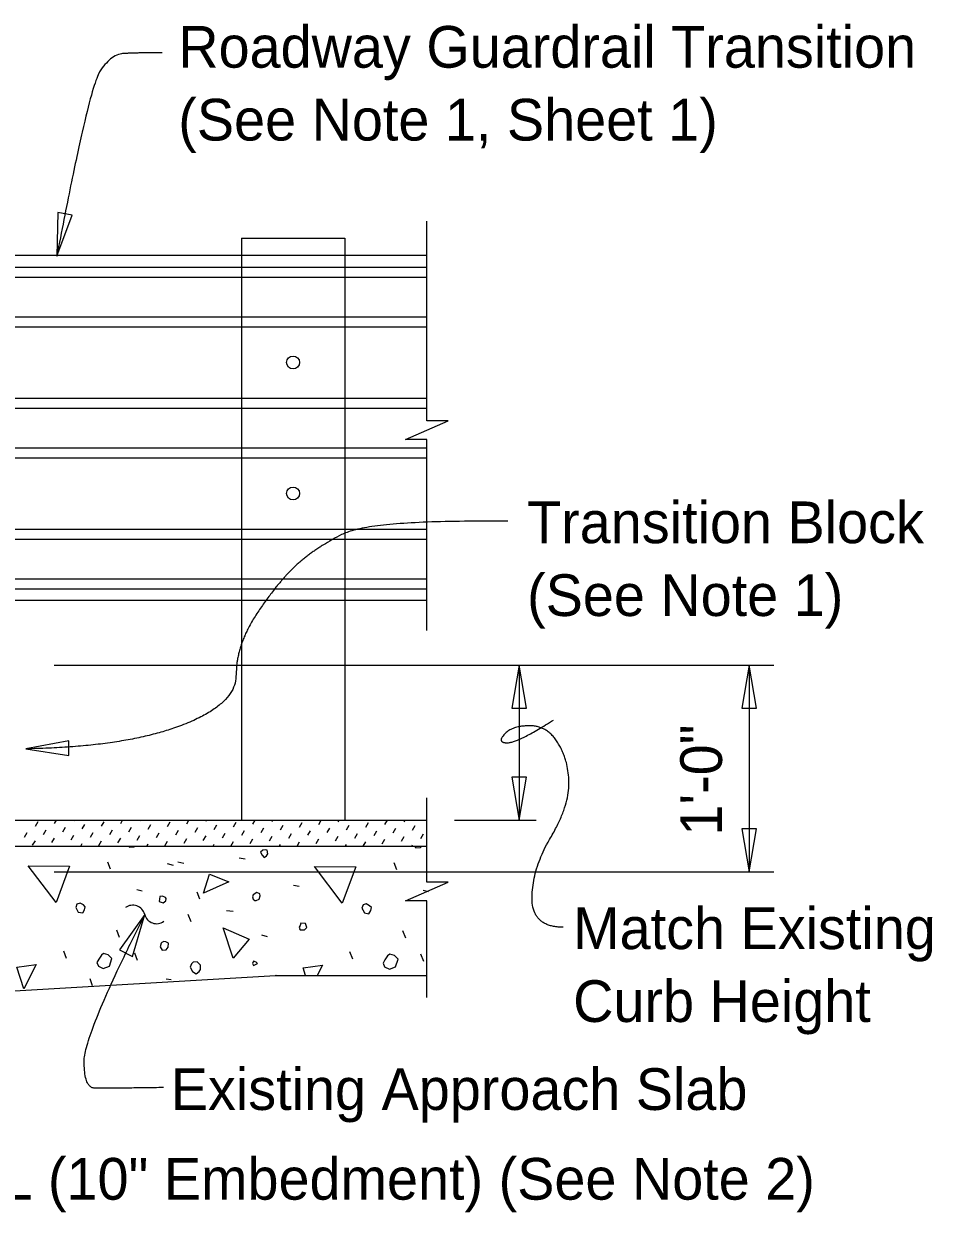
# Model space of a CAD drawing. Extents: x 21526.6 to 21598.7, y 56118.9 to 56155.9.
# Drawn here: x 21539.73 to 21544.13, y 56132.57 to 56138.31 of the extents above; entities that cross this region are included whole.
import ezdxf

# ---------------------------------------------------------------- set-up
doc = ezdxf.new("R2010")
doc.units = 0
for name, color, linetype in [('AdhocPoint_dp', 7, 'Continuous'), ('Border', 7, 'Continuous'), ('Patterning', 7, 'Continuous'), ('PlotBorder_dp', 7, 'Continuous'), ('SheetBorder_dp', 7, 'Continuous')]:
    doc.layers.add(name, color=color, linetype=linetype)

msp = doc.modelspace()

# ---------------------------------------------------------------- linework, layer by layer
at = {"layer": 'AdhocPoint_dp'}
for p, q in [((21535.7321, 56134.4601), (21541.6829, 56134.4601)), ((21537.6185, 56134.335), (21541.6829, 56134.335)), ((21536.7321, 56133.4601), (21540.9521, 56133.71)), ((21540.9521, 56133.7101), (21541.6829, 56133.7101))]:
    msp.add_line(p, q, dxfattribs=at)
at = {"layer": 'Patterning'}
for p, q in [((21540.7867, 56137.2725), (21540.7867, 56134.4601)), ((21540.7867, 56137.2725), (21541.2867, 56137.2725)), ((21541.2867, 56137.2725), (21541.2867, 56134.4601)), ((21539.7909, 56134.4317), (21539.8039, 56134.4541)), ((21539.884, 56134.4447), (21539.8929, 56134.46)), ((21539.9771, 56134.4577), (21539.9785, 56134.46)), ((21540.1103, 56134.4306), (21540.1232, 56134.4529)), ((21540.2034, 56134.4435), (21540.2129, 56134.46)), ((21540.2965, 56134.4565), (21540.2985, 56134.46)), ((21540.4297, 56134.4294), (21540.4426, 56134.4518)), ((21540.5228, 56134.4423), (21540.533, 56134.46)), ((21540.6159, 56134.4553), (21540.6186, 56134.46)), ((21540.749, 56134.4282), (21540.762, 56134.4506)), ((21540.8421, 56134.4412), (21540.8531, 56134.46)), ((21540.9352, 56134.4541), (21540.9387, 56134.46)), ((21541.0684, 56134.427), (21541.0814, 56134.4494)), ((21541.1615, 56134.44), (21541.1731, 56134.46)), ((21541.2546, 56134.4529), (21541.2587, 56134.46)), ((21541.3878, 56134.4258), (21541.4008, 56134.4482)), ((21541.4809, 56134.4388), (21541.4932, 56134.46)), ((21541.574, 56134.4518), (21541.5788, 56134.46)), ((21539.7379, 56134.3787), (21539.7508, 56134.4011)), ((21539.831, 56134.3917), (21539.8439, 56134.4141)), ((21539.9241, 56134.4046), (21539.937, 56134.427)), ((21539.9641, 56134.3646), (21539.9771, 56134.387)), ((21540.0172, 56134.4176), (21540.0301, 56134.44)), ((21540.0572, 56134.3775), (21540.0702, 56134.3999)), ((21540.1504, 56134.3905), (21540.1633, 56134.4129)), ((21540.2435, 56134.4034), (21540.2564, 56134.4258)), ((21540.3366, 56134.4164), (21540.3495, 56134.4388)), ((21540.3766, 56134.3763), (21540.3896, 56134.3987)), ((21540.4697, 56134.3893), (21540.4827, 56134.4117)), ((21540.5628, 56134.4023), (21540.5758, 56134.4247)), ((21540.6559, 56134.4152), (21540.6689, 56134.4376)), ((21540.696, 56134.3752), (21540.709, 56134.3976)), ((21540.7891, 56134.3881), (21540.8021, 56134.4105)), ((21540.8822, 56134.4011), (21540.8952, 56134.4235)), ((21540.9753, 56134.4141), (21540.9883, 56134.4364)), ((21541.0154, 56134.374), (21541.0283, 56134.3964)), ((21541.1085, 56134.387), (21541.1214, 56134.4093)), ((21541.2016, 56134.3999), (21541.2145, 56134.4223)), ((21541.2947, 56134.4129), (21541.3077, 56134.4353)), ((21541.3348, 56134.3728), (21541.3477, 56134.3952)), ((21541.4279, 56134.3858), (21541.4408, 56134.4082)), ((21541.521, 56134.3987), (21541.5339, 56134.4211)), ((21541.6141, 56134.4117), (21541.627, 56134.4341)), ((21541.6541, 56134.3716), (21541.6671, 56134.394)), ((21539.7779, 56134.3386), (21539.7909, 56134.361)), ((21539.871, 56134.3516), (21539.884, 56134.374)), ((21540.0103, 56134.335), (21540.0172, 56134.3469)), ((21540.0973, 56134.3375), (21540.1103, 56134.3598)), ((21540.1904, 56134.3504), (21540.2034, 56134.3728)), ((21540.2835, 56134.3634), (21540.2965, 56134.3858)), ((21540.3304, 56134.335), (21540.3366, 56134.3457)), ((21540.4167, 56134.3363), (21540.4297, 56134.3587)), ((21540.5098, 56134.3492), (21540.5228, 56134.3716)), ((21540.6029, 56134.3622), (21540.6159, 56134.3846)), ((21540.6504, 56134.335), (21540.6559, 56134.3445)), ((21540.7361, 56134.3351), (21540.749, 56134.3575)), ((21540.8292, 56134.3481), (21540.8421, 56134.3705)), ((21540.9223, 56134.361), (21540.9352, 56134.3834)), ((21540.9705, 56134.335), (21540.9753, 56134.3433)), ((21541.0561, 56134.335), (21541.0684, 56134.3563)), ((21541.1486, 56134.3469), (21541.1615, 56134.3693)), ((21541.2417, 56134.3598), (21541.2546, 56134.3822)), ((21541.2905, 56134.335), (21541.2947, 56134.3422)), ((21541.3761, 56134.335), (21541.3878, 56134.3551)), ((21541.4679, 56134.3457), (21541.4809, 56134.3681)), ((21541.561, 56134.3587), (21541.574, 56134.3811)), ((21541.6106, 56134.335), (21541.6141, 56134.341)), ((21540.7756, 56134.2785), (21540.8056, 56134.2732)), ((21540.1542, 56134.2237), (21540.1418, 56134.2573)), ((21540.4282, 56134.2502), (21540.4565, 56134.2431)), ((21540.4799, 56134.2595), (21540.5082, 56134.2524)), ((21541.5375, 56134.2202), (21541.5251, 56134.2537)), ((21540.2815, 56134.1247), (21540.308, 56134.1194)), ((21540.586, 56134.0783), (21540.5736, 56134.1119)), ((21541.0389, 56134.1459), (21541.0655, 56134.1406)), ((21541.6647, 56134.1212), (21541.6913, 56134.1159)), ((21540.5435, 56133.9687), (21540.5294, 56134.004)), ((21540.7154, 56134.0239), (21540.7473, 56134.0204)), ((21540.1984, 56133.8931), (21540.1842, 56133.9285)), ((21540.8834, 56133.9055), (21540.9117, 56133.8984)), ((21541.5817, 56133.8896), (21541.5675, 56133.9249)), ((21539.9421, 56133.7924), (21539.9279, 56133.8277)), ((21540.2854, 56133.7813), (21540.2713, 56133.8167)), ((21541.3253, 56133.7888), (21541.3112, 56133.8242)), ((21541.6687, 56133.7778), (21541.6546, 56133.8131)), ((21540.0676, 56133.6598), (21540.0552, 56133.6934)), ((21540.4233, 56133.6929), (21540.4481, 56133.6894))]:
    msp.add_line(p, q, dxfattribs=at)
for points in [[(21540.2429, 56134.335), (21540.2461, 56134.3298), (21540.2691, 56134.3315), (21540.2725, 56134.335)], [(21541.624, 56134.335), (21541.6294, 56134.3262), (21541.6524, 56134.328), (21541.6594, 56134.335)], [(21540.8869, 56134.2909), (21540.8975, 56134.2803), (21540.9081, 56134.2873), (21540.9152, 56134.2979), (21540.9117, 56134.3156), (21540.9028, 56134.3174), (21540.8905, 56134.3156), (21540.8799, 56134.305), (21540.8869, 56134.2909)], [(21539.8908, 56134.0628), (21539.7564, 56134.2396), (21539.9562, 56134.2378), (21539.8908, 56134.0628)], [(21541.2741, 56134.0593), (21541.1397, 56134.2361), (21541.3395, 56134.2343), (21541.2741, 56134.0593)], [(21540.6041, 56134.107), (21540.6324, 56134.1989), (21540.7261, 56134.1618), (21540.6041, 56134.107)], [(21540.8516, 56134.0717), (21540.8586, 56134.0717), (21540.8728, 56134.0787), (21540.8781, 56134.0946), (21540.8763, 56134.1035), (21540.8622, 56134.1106), (21540.8445, 56134.0999), (21540.841, 56134.0893), (21540.8445, 56134.0787), (21540.8516, 56134.0717)], [(21539.9898, 56134.031), (21539.9986, 56134.0151), (21540.0198, 56134.0116), (21540.0287, 56134.0275), (21540.0322, 56134.0416), (21540.0234, 56134.0505), (21540.0075, 56134.0593), (21539.9915, 56134.054), (21539.9862, 56134.0381), (21539.9898, 56134.031)], [(21540.3893, 56134.0664), (21540.4087, 56134.0611), (21540.4211, 56134.0699), (21540.4229, 56134.0823), (21540.4193, 56134.0858), (21540.4052, 56134.0929), (21540.3928, 56134.0911), (21540.3911, 56134.0787), (21540.3893, 56134.0664)], [(21541.3731, 56134.0275), (21541.3819, 56134.0116), (21541.4031, 56134.008), (21541.4119, 56134.0239), (21541.4155, 56134.0381), (21541.4066, 56134.0469), (21541.3907, 56134.0558), (21541.3748, 56134.0505), (21541.3695, 56134.0345), (21541.3731, 56134.0275)], [(21540.7468, 56133.7937), (21540.6991, 56133.9404), (21540.8246, 56133.8856), (21540.7468, 56133.7937)], [(21541.0708, 56133.9302), (21541.092, 56133.9302), (21541.1026, 56133.9409), (21541.0973, 56133.9603), (21541.0743, 56133.9621), (21541.0708, 56133.9515), (21541.0655, 56133.9426), (21541.0708, 56133.9302), (21541.0672, 56133.9338)], [(21540.395, 56133.8485), (21540.4039, 56133.8326), (21540.4233, 56133.8343), (21540.4322, 56133.8467), (21540.4339, 56133.8662), (21540.4216, 56133.8715), (21540.4127, 56133.8732), (21540.4021, 56133.8697), (21540.3986, 56133.8662), (21540.395, 56133.8485)], [(21540.0958, 56133.7552), (21540.1188, 56133.7429), (21540.1489, 56133.7552), (21540.1613, 56133.7924), (21540.1436, 56133.81), (21540.1206, 56133.8153), (21540.11, 56133.8083), (21540.0976, 56133.7888), (21540.0888, 56133.7729), (21540.0958, 56133.7552)], [(21539.7352, 56133.6456), (21539.7016, 56133.7499), (21539.7953, 56133.7623), (21539.7352, 56133.6456)], [(21540.54, 56133.7495), (21540.5506, 56133.7283), (21540.5683, 56133.7177), (21540.5824, 56133.7283), (21540.5895, 56133.7389), (21540.5895, 56133.7601), (21540.5736, 56133.776), (21540.5541, 56133.7742), (21540.5453, 56133.7654), (21540.54, 56133.7495)], [(21540.8458, 56133.7583), (21540.8653, 56133.7672), (21540.8582, 56133.7742), (21540.8458, 56133.7795), (21540.8405, 56133.7672), (21540.8458, 56133.7583)], [(21541.0966, 56133.71), (21541.0849, 56133.7464), (21541.1786, 56133.7588), (21541.1535, 56133.71)], [(21541.4791, 56133.7517), (21541.5021, 56133.7393), (21541.5322, 56133.7517), (21541.5445, 56133.7888), (21541.5269, 56133.8065), (21541.5039, 56133.8118), (21541.4933, 56133.8047), (21541.4809, 56133.7853), (21541.4721, 56133.7694), (21541.4791, 56133.7517)], [(21540.9547, 56133.71), (21540.9537, 56133.7106), (21540.9522, 56133.71)]]:
    msp.add_lwpolyline(points, dxfattribs=at)
at = {"layer": 'PlotBorder_dp'}
for p, q in [((21539.8821, 56135.2101), (21543.3608, 56135.2101)), ((21542.129, 56135.2101), (21542.129, 56134.4601)), ((21543.2414, 56135.2102), (21543.2414, 56134.2102)), ((21541.8169, 56134.4601), (21542.2116, 56134.4601)), ((21539.8821, 56134.2101), (21543.3608, 56134.2101))]:
    msp.add_line(p, q, dxfattribs=at)
for points in [[(21539.8946, 56137.1866), (21539.9683, 56137.3845), (21539.899, 56137.3977)], [(21542.129, 56135.2101), (21542.0937, 56135.0018), (21542.1642, 56135.0018)], [(21543.2414, 56135.2102), (21543.2061, 56135.0019), (21543.2766, 56135.0019)], [(21539.7444, 56134.8051), (21539.9532, 56134.7733), (21539.9521, 56134.8439)], [(21542.129, 56134.4601), (21542.1642, 56134.6683), (21542.0937, 56134.6683)], [(21543.2414, 56134.2102), (21543.2766, 56134.4184), (21543.2061, 56134.4184)], [(21540.3202, 56134.0044), (21540.1971, 56133.8327), (21540.2605, 56133.8018)]]:
    msp.add_lwpolyline(points, close=True, dxfattribs=at)
for points in [[(21541.6829, 56135.3777), (21541.6829, 56136.3003), (21541.5795, 56136.3003), (21541.6829, 56136.3453), (21541.7862, 56136.3903), (21541.6829, 56136.3903), (21541.6829, 56137.3551)], [(21541.6829, 56133.6036), (21541.6829, 56134.0708), (21541.5795, 56134.0708), (21541.6829, 56134.1158), (21541.7862, 56134.1608), (21541.6829, 56134.1608), (21541.6829, 56134.5682)]]:
    msp.add_lwpolyline(points, dxfattribs=at)
for centre, start, end in [((21540.2618, 56133.9896), 14.54134, 126.26856), ((21540.3772, 56134.0195), 194.54134, 306.26856)]:
    msp.add_arc(centre, 0.0596, start, end, dxfattribs=at)
for points in [[(21540.4034, 56138.1693), (21540.2833, 56138.1693), (21540.1525, 56138.1622), (21540.0465, 56137.9819), (21539.8946, 56137.1866)], [(21542.0754, 56135.9047), (21541.4139, 56135.9116), (21541.1398, 56135.7744), (21540.9568, 56135.6032), (21540.7613, 56135.3058), (21540.7613, 56135.0162), (21540.2137, 56134.8128), (21539.7444, 56134.8049)], [(21542.3427, 56133.9425), (21542.1919, 56133.9425), (21542.1919, 56134.2238), (21542.3701, 56134.5256), (21542.3701, 56134.7451), (21542.2673, 56134.9166), (21542.0959, 56134.9166), (21542.0206, 56134.8343), (21542.1234, 56134.8343), (21542.2947, 56134.944)], [(21540.4101, 56133.1678), (21540.1274, 56133.1634), (21540.0268, 56133.1666), (21540.0268, 56133.4222), (21540.3202, 56134.0043)]]:
    msp.add_open_spline(points, degree=2, dxfattribs=at)
at = {"layer": 'SheetBorder_dp'}
for p, q in [((21541.6829, 56137.1892), (21534.1592, 56137.1892)), ((21534.1592, 56137.1336), (21541.6829, 56137.1336)), ((21534.1592, 56137.0854), (21541.6829, 56137.0854)), ((21534.1592, 56136.8926), (21541.6829, 56136.8926)), ((21534.1592, 56136.8444), (21541.6829, 56136.8444)), ((21534.1592, 56136.5004), (21541.6829, 56136.5004)), ((21534.1592, 56136.4522), (21541.6829, 56136.4522)), ((21534.1592, 56136.2594), (21541.6829, 56136.2594)), ((21534.1592, 56136.2112), (21541.6829, 56136.2112)), ((21534.1592, 56135.8673), (21541.6829, 56135.8673)), ((21534.1592, 56135.8191), (21541.6829, 56135.8191)), ((21534.1592, 56135.6262), (21541.6829, 56135.6262)), ((21534.1592, 56135.578), (21541.6829, 56135.578)), ((21541.6829, 56135.5225), (21534.1592, 56135.5225))]:
    msp.add_line(p, q, dxfattribs=at)
for centre in [(21541.0367, 56136.6724), (21541.0367, 56136.0393)]:
    msp.add_circle(centre, 0.0312, dxfattribs=at)

# ---------------------------------------------------------------- texts
at = {"layer": 'Border'}
msp.add_text('1\'-0"', height=0.2016, rotation=90, dxfattribs=at).set_placement((21543.1097, 56134.3857))
for s, p in [('Existing Approach Slab', (21540.4455, 56133.0596)), ('Dowel Bars 4L (10" Embedment) (See Note 2)', (21538.0238, 56132.6259))]:
    msp.add_text(s, height=0.2016, dxfattribs=at).set_placement(p)
at = {"layer": 'PlotBorder_dp'}
for s, p in [('Roadway Guardrail Transition', (21540.4819, 56138.0972)), ('(See Note 1, Sheet 1)', (21540.4819, 56137.7452)), ('Transition Block', (21542.1678, 56135.799)), ('(See Note 1)', (21542.1678, 56135.447)), ('Match Existing ', (21542.3904, 56133.8368)), ('Curb Height', (21542.3904, 56133.4848))]:
    msp.add_text(s, height=0.2016, dxfattribs=at).set_placement(p)

doc.saveas('drawing.dxf')
